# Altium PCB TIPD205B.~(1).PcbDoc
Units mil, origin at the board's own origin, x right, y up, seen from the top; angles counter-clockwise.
Board outline 684.25 x 4724.41 mil, 4 copper layers (Top Layer, Signal Layer 1, Signal Layer 2, Bottom Layer), stack 61.6 mil thick; 36 components, 24 nets, 156 pads, 59 vias.
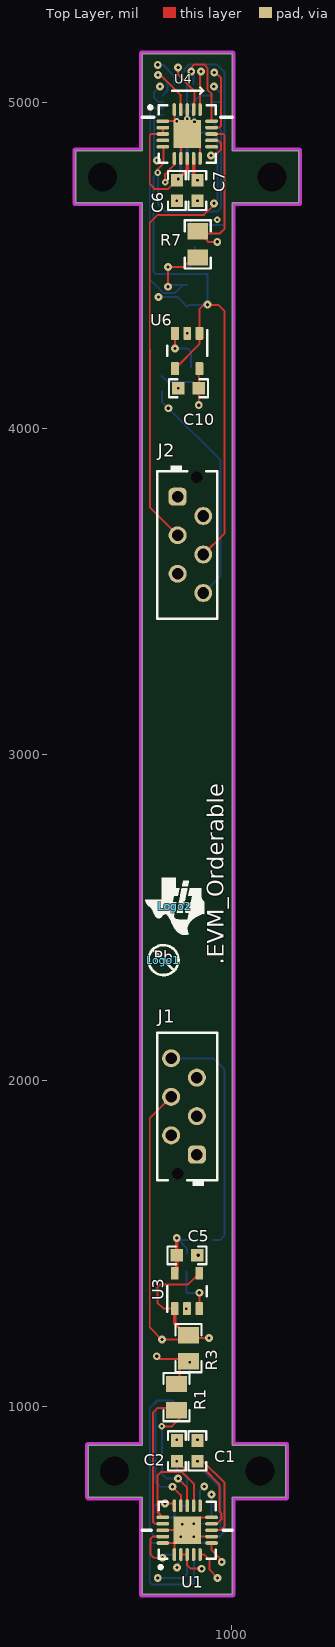
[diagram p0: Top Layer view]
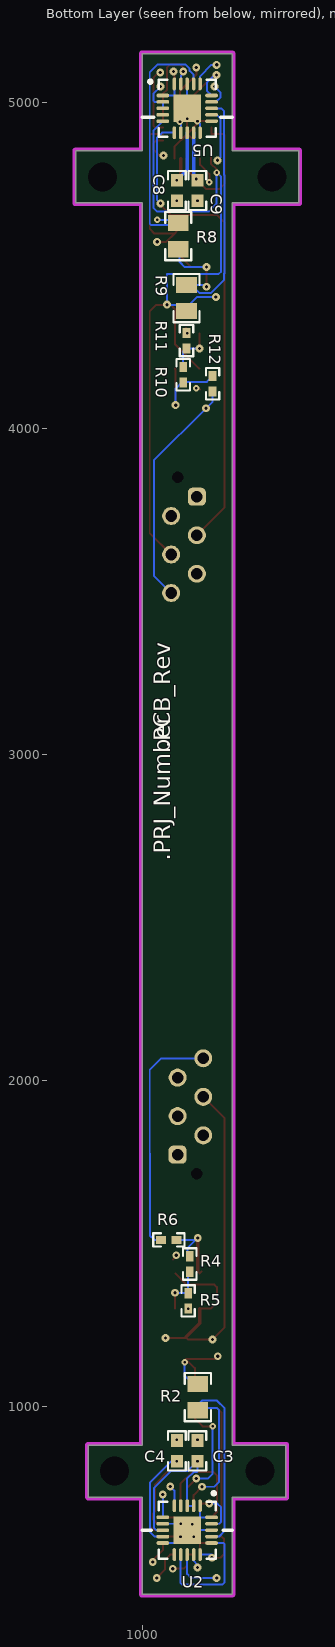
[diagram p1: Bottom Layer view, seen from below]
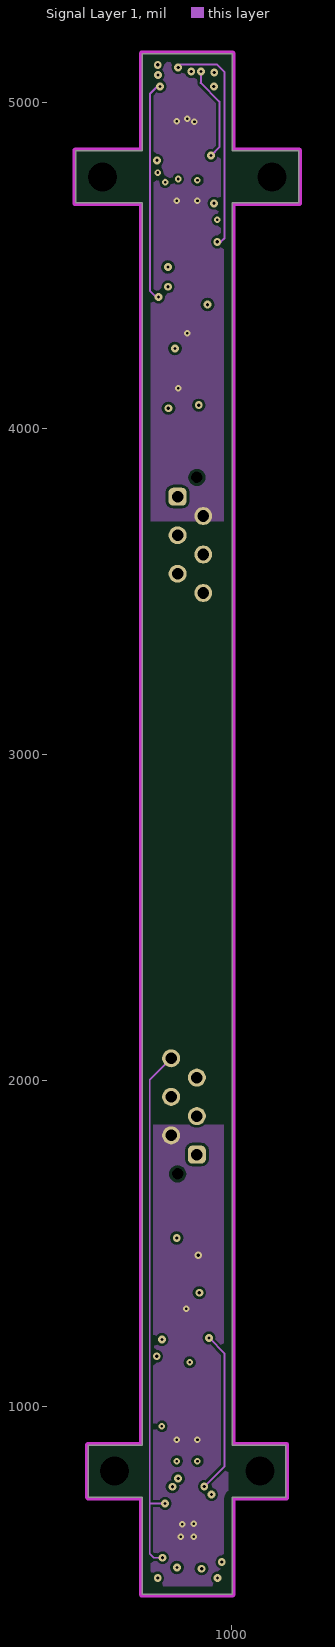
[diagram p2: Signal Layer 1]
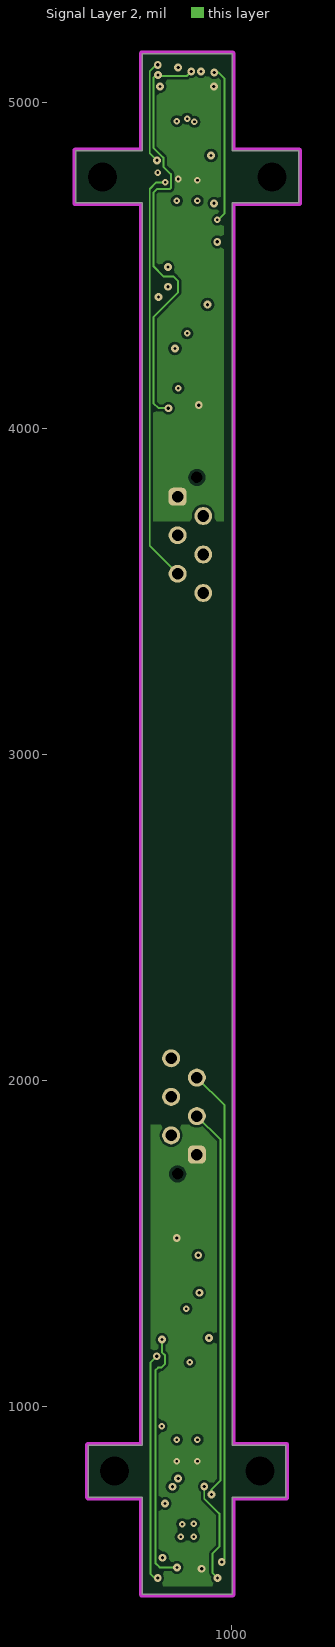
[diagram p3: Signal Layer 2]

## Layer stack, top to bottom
Top Solder: solder mask 0.4, Solder Resist, Dk 3.5
Top Layer: signal copper 1.4
Dielectric 1: prepreg 8, FR-4, Dk 4.2
Signal Layer 1: signal copper 1.4
Dielectric 2: core 40, FR-4, Dk 4.2
Signal Layer 2: signal copper 1.4
Dielectric 3: prepreg 8, FR-4, Dk 4.2
Bottom Layer: signal copper 1.4
Bottom Solder: solder mask 0.4, Solder Resist, Dk 3.5

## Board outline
725,425 725,723.03 560.04,723.03 560.04,882.87 725,882.87 725,4691.54 520.67,4691.54 520.67,4851.38 725,4851.38 725,5149.41 1000.59,5149.41 1000.59,4851.38 1204.92,4851.38 1204.92,4691.54 1000.59,4691.54 1000.59,882.87 1165.55,882.87 1165.55,723.03 1000.59,723.03 1000.59,425

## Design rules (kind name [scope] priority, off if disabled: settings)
AcuteAngle [All] p1: minimum=4.50000000000000E+0001 checktracksonly=FALSE
AssemblyTestPointUsage [All] p1: valid=2
Clearance Clearance_Keepouts [((IsTrack Or IsArc) And Not InPoly) And IsFree and IsKeepOut vs ((IsTrack Or IsArc) And Not InPoly) And IsFree and IsKeepOut] p1: gap=0
Clearance Clearance_BoardEdge_MountingHoles [OnCopper and InComponentClass('Mounting Holes') vs IsKeepOut] p2: gap=40
Clearance Clearance_BoardEdge_Poly [OnCopper and InPoly vs IsKeepOut] p3: gap=25
Clearance Clearance_BoardEdge [OnCopper and Not InComponentClass('Logo') and not InComponentClass('FiducialMark') and not InRegion(1000,500,4000,800) and Not IsKeepout vs IsKeepOut] p4: gap=20
Clearance Clearance_Poly [InPolygon] p5: gap=8
Clearance [All] p6: gap=4.9
ComponentClearance ComponentClearance_MountingHoles_FiducialMarks [InComponentClass('Mounting Holes') vs InComponentClass('FiducialMark')] p1: gap=7 collisioncheckmode=3 verticalgap=10 showdistances=FALSE
ComponentClearance ComponentClearance_Shunt [InComponentClass('Header') vs InComponentClass('Shunt')] p2: gap=0 collisioncheckmode=3 verticalgap=0 showdistances=FALSE
ComponentClearance ComponentClearance_Logo [InComponentClass('Logo')] p3: gap=0 collisioncheckmode=3 verticalgap=0 showdistances=FALSE
ComponentClearance ComponentClearance_ScrewToNut [(HasFootprint('NY PMS 440 0025 PH')) vs (HasFootprint('Keystone_1902C'))] p4: gap=5 collisioncheckmode=3 verticalgap=10 showdistances=FALSE
ComponentClearance ComponentClearance_MountingHoles [InComponentClass('Mounting Holes') vs InAnyComponent And Not InComponentClass('Hardware')] p5: gap=10 collisioncheckmode=3 verticalgap=10 showdistances=TRUE
ComponentClearance ComponentClearance_SmallPassives [HasFootprint('0201*') or HasFootprint('0402*') or HasFootprint('0508') or HasFootprint('0603*') or HasFootprint('0612') or HasFootprint('0805*') or HasFootprint('0815*') or HasFootprint('0830*') or HasFootprint('1206*') or HasFootprint('1210*') or HasFootprint('1808*') or HasFootprint('1812*') or HasFootprint('1825*') or HasFootprint('2010*') or HasFootprint('2220*') or HasFootprint('2225*') or HasFootprint('2512*') or HasFootprint('2728*') or HasFootprint('3518*') vs HasFootprint('0201*') or HasFootprint('0402*') or HasFootprint('0508') or HasFootprint('0603*') or HasFootprint('0612') or HasFootprint('0805*') or HasFootprint('0815*') or HasFootprint('0830*') or HasFootprint('1206*') or HasFootprint('1210*') or HasFootprint('1808*') or HasFootprint('1812*') or HasFootprint('1825*') or HasFootprint('2010*') or HasFootprint('2220*') or HasFootprint('2225*') or HasFootprint('2512*') or HasFootprint('2728*') or HasFootprint('3518*')] p6: gap=20 collisioncheckmode=3 verticalgap=10 showdistances=FALSE
ComponentClearance ComponentClearance_THtoSMT [IsThruComponent And  Not InComponentClass('Hardware') vs IsSMTComponent And  Not InComponentClass('Hardware')] p7: gap=10 collisioncheckmode=3 verticalgap=10 showdistances=FALSE
ComponentClearance ComponentClearance_THtoTH [IsThruComponent vs IsThruComponent] p8: gap=10 collisioncheckmode=3 verticalgap=10 showdistances=FALSE
ComponentClearance [Not InComponentClass('Hardware') And  Not InComponentClass('Logo') vs Not InComponentClass('Hardware') And  Not InComponentClass('Logo')] p9: gap=7 collisioncheckmode=3 verticalgap=7 showdistances=TRUE
DiffPairsRouting [All] p1: maxlimit=100 minlimit=10 mostfreqgap=10 toplayer_minwidth=15 toplayer_maxwidth=15 toplayer_prefwidth=15 midlayer1_minwidth=15 midlayer1_maxwidth=15 midlayer1_prefwidth=15 midlayer2_minwidth=15 midlayer2_maxwidth=15 midlayer2_prefwidth=15 bottomlayer_minwidth=15 bottomlayer_maxwidth=15 bottomlayer_prefwidth=15 maxuncoupledlength=1000
FabricationTestPointUsage TestPointUsage [All] p1: valid=2 allowmultiple=FALSE
FabricationTestpoint Testpoint [All] p1: side=3 testpointundercomponent=TRUE minsize=40 maxsize=100 preferedsize=60 minholesize=0 maxholesize=40 preferedholesize=32 testpointgrid=1 allowsidetop=TRUE allowsidebottom=TRUE usegrid=TRUE gridtolerance=0.01
FanoutControl Fanout_LCC [IsLCC] p1: bgadir=Out bgaviamode=Centered fanoutstyle=Auto fanoutdirection=Alternating viagrid=1 // Fanout_LCC (Default Rule)
FanoutControl Fanout_BGA [IsBGA] p2: bgadir=Out bgaviamode=Centered fanoutstyle=Auto fanoutdirection=Alternating viagrid=1 // Fanout_BGA (Default Rule)
FanoutControl Fanout_Default [All] p4: bgadir=Out bgaviamode=Centered fanoutstyle=Auto fanoutdirection=Alternating viagrid=1 // Fanout_Default (Default Rule)
FanoutControl Fanout_Small [(CompPinCount < 5)] p5: bgadir=Out bgaviamode=Centered fanoutstyle=Auto fanoutdirection=OutThenIn viagrid=1 // Fanout_Small (Default Rule)
Height [All] p1 off: minheight=0 maxheight=1000 prefheight=500
HoleSize [All] p1: absolutevalues=TRUE maxlimit=251 minlimit=8 maxpercent=80.000 minpercent=20.000
MinimumAnnularRing MinimumAnnularRing_ThermalPadVias [IsVia and InAnyComponent] p1: minimumring=5.91
MinimumAnnularRing [All] p2: minimumring=6
MinimumSolderMaskSliver MinimumSolderMaskSliver_Logo [InComponentClass('Logo') vs InComponentClass('Logo')] p1: minsoldermaskwidth=0.7
MinimumSolderMaskSliver [All] p2: minsoldermaskwidth=3.1
PlaneConnect [All] p1: planeconnectstyle=Relief reliefexpansion=10 reliefentries=4 reliefconductorwidth=10 reliefairgap=10
PolygonConnect [All] p1: connectstyle=Direct reliefconductorwidth=10 reliefentries=4 polygonreliefangle="90 Angle" airgapwidth=10
RoutingVias ThermalPadVias [IsVia and InAnyComponent] p1: holewidth=8 width=19.68 viastyle="Through Hole" minholewidth=7.87 minwidth=19.68 maxholewidth=999 maxwidth=999
RoutingVias [All] p2: holewidth=10 width=24 viastyle="Through Hole" minholewidth=8 minwidth=20 maxholewidth=999 maxwidth=999
SilkToSilkClearance SilkToSilkClearance_Pb-FreeLogo [(HasFootprint('Pb-Free_Overlay_Medium') OR HasFootprint('Pb-Free_Overlay_Small')) vs (HasFootprint('Pb-Free_Overlay_Medium') OR HasFootprint('Pb-Free_Overlay_Small'))] p1 off: silktosilkclearance=0
SilkToSilkClearance [All] p2 off: silktosilkclearance=3
SilkToSolderMaskClearance SilkToComonentPadClearance [IsPad and InAnycomponent vs Not InComponentClass('Hardware')] p1: minsilkscreentomaskgap=3 clearancetoexposedcopper=TRUE
SilkToSolderMaskClearance "Silk to Solder Mask Opening" [Not InComponentClass('Hardware') vs Not InComponentClass('Hardware')] p2: minsilkscreentomaskgap=3 clearancetoexposedcopper=FALSE
SolderMaskExpansion [All] p1: expansion=0
Width [All] p1: maxlimit=100 minlimit=6 preferedwidth=6 minimp=50.000000 maximp=50.000000 favimp=50.000000 checkconnectedcopper=TRUE
15 further rules are at their usual default settings.

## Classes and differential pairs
component class Logo: Logo2
component class TIPD205BHW: Logo1 Logo2 Logo3 Logo? ZZ2 ZZ3 ZZ4
component class AssemblyNote: ZZ2 ZZ3 ZZ4

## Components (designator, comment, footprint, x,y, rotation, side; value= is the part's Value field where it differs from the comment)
C1 "C0603C105K3RACTU" 0603 894.29,864.92 r90 top
C2 "C0603C105K3RACTU" 0603 831.3,864.92 r270 top
C3 "C0603C105K3RACTU" 0603 831.3,864.92 r90 bottom
C4 "C0603C105K3RACTU" 0603 894.29,864.92 r270 bottom
C5 "C0603C105K3RACTU" 0603 862.05,1464.61 r0 top
C6 "C0603C105K3RACTU" 0603 831.3,4729.72 r270 top
C7 "C0603C105K3RACTU" 0603 894.29,4729.7 r90 top
C8 "C0603C105K3RACTU" 0603 894.29,4729.7 r270 bottom
C9 "C0603C105K3RACTU" 0603 831.3,4729.72 r90 bottom
C10 "C0603C105K3RACTU" 0603 866.73,4123.43 r180 top
J1 "292207-6" TE_292207-6 862.8,1921.06 r90 top
J2 "292207-6" TE_292207-6 862.8,3643.11 r270 top
Logo1 "Pb-Free Symbol" Pb-Free_Overlay_Small 790,2370 r0 top
Logo2 "Texas Instruments" TI_Symbol_Overlay_Small 825,2535 r0 top
Logo3 "FCC disclaimer" FCC_disclaimer -2112.55,3535 r180 bottom
R1 "RC0805FR-075R11L" 0805_HV 830,1030 r270 top
R2 "RC0805FR-075R11L" 0805_HV 830,1030 r90 bottom
R3 "RT0805BRD0749R9L" 0805_HV 866.73,1179.88 r270 top
R4 "CRCW040210K0FKED" 0402 855,1437.99 r90 bottom
R5 "CRCW040210K0FKED" 0402 860,1325 r90 bottom
R6 "CRCW040210K0FKED" 0402 919.25,1511.89 r180 bottom
R7 "RC0805FR-075R11L" 0805_HV 895,4564.39 r90 top
R8 "RC0805FR-075R11L" 0805_HV 890,4589.98 r270 bottom
R9 "RT0805BRD0749R9L" 0805_HV 865,4400 r90 bottom
R10 "CRCW040210K0FKED" 0402 875,4164.76 r270 bottom
R11 "CRCW040210K0FKED" 0402 865,4269.12 r270 bottom
R12 "CRCW040210K0FKED" 0402 785,4137.17 r90 bottom
U1 "DRV425RTJR" RTJ20_no_vias 862.8,621.85 r90 top
U2 "DRV425RTJR" RTJ20_no_vias 862.8,621.85 r270 bottom
U3 "OPA320AIDBVT" DBV0005A_N 862.05,1355.32 r90 top
U4 "DRV425RTJR" RTJ20_no_vias 862.8,4902.95 r0 top
U5 "DRV425RTJR" RTJ20_no_vias 862.8,4981.69 r180 bottom
U6 "OPA320AIDBVT" DBV0005A_N 862.8,4237.6 r270 top
ZZ2 "This Assembly Note will show in the PcbDoc and associated outputs" AssemblyNote 2730,4704.11 r0 top
ZZ3 "This Assembly Note will show in the PcbDoc and associated outputs" AssemblyNote 2730,4615.56 r0 top
ZZ4 "This Assembly Note will show in the PcbDoc and associated outputs" AssemblyNote 2730,4527 r0 top

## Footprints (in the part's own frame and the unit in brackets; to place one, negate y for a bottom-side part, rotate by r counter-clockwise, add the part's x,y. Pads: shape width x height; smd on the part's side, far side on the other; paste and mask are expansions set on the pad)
0402 [mm] "0402 from SM-752 data"
  rect 0.8x0.6 smd: 1(-0.6,0) 2(0.6,0)
  silkscreen extent -1.22,-0.52 1.22,0.52, body extent -0.55,-0.3 0.55,0.3, height 0.6
0603 [mm] "0603 from SM-752 data"
  rect 1x0.95 smd: 1(-0.8,0) 2(0.8,0)
  silkscreen extent -1.52,-0.69 1.52,0.69, body extent -0.87,-0.47 0.87,0.47, height 1
0805_HV [mil] "0805 with 30mil clearance between pads"
  rect 50x63 smd: 1(-40,0) 2(40,0)
  silkscreen extent -74,-40 74,40, body extent -43,-29 43,29, height 57
AssemblyNote [mil] "Assembly Note"
DBV0005A_N [mm] "SOT23, 5-Leads, Body 2.9x1.6mm, Pitch 0.95mm, Lead Span 2.8mm, IPC Medium Density"
  rrect17% 1x0.6 smd: 1(-1.375,0.95) 2(-1.375,0) 3(-1.375,-0.95) 4(1.375,-0.95) 5(1.375,0.95)
  silkscreen extent -1.63,-1.55 0.38,1.55, body extent -1.42,-1.46 1.42,1.46, height 1.09
FCC_disclaimer [mil]
Pb-Free_Overlay_Small [mil]
  silkscreen extent -46,-46 46,46
RTJ20_no_vias [mm]
  oval 1x0.28 smd paste-0.025 mask+0.07: 1(-1.9,1) 2(-1.9,0.5) 3(-1.9,0) 4(-1.9,-0.5) 5(-1.9,-1) 11(1.9,-1) 12(1.9,-0.5) 13(1.9,0) 14(1.9,0.5) 15(1.9,1)
  oval 0.28x1 smd paste-0.025 mask+0.07: 6(-1,-1.9) 7(-0.5,-1.9) 8(0,-1.9) 9(0.5,-1.9) 10(1,-1.9) 16(1,1.9) 17(0.5,1.9) 18(0,1.9) 19(-0.5,1.9) 20(-1,1.9)
  rect 2.15x2.15 smd paste-1.075 mask+0.07: 21(0,0)
  silkscreen extent -3,-2.23 2.23,2.22, body extent -2.07,-2.08 2.08,2.07, height 0.8
TE_292207-6 [mm] "Header(shrouded), 1.5mm, 6x1, TH"
  rrect50% 1.4x1.4 hole 0.9: 1(-3.75,-0.75)
  round 1.4 hole 0.9: 2(-2.25,1.25) 3(-0.75,-0.75) 4(0.75,1.25) 5(2.25,-0.75) 6(3.75,1.25)
  round 0 hole 0.9 unplated: MH(-5.25,0.75)
  silkscreen extent -6.2,-2.35 5.75,2.35, body extent -5.75,-2.35 5.75,2.35, height 6.9
TI_Symbol_Overlay_Small [mil]
  silkscreen extent -90,-88 91,88

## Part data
C1 C2 C3 C4 C5 C6 C7 C8 C9 C10: "CAP, CERM, 1 µF, 25 V, +/- 10%, X7R, 0603"
J1 J2: "Header(shrouded), 1.5mm, 6x1, Tin, TH"
Logo1: library part Pb-Free
Logo2: library part TI_Logo, "Texas Instrument Corporate Signature"
Logo3: library part FCC_disclaimer, "FCC_disclaimer"
R1 R2 R7 R8: "RES, 5.11, 1%, 0.125 W, 0805"
R3 R9: "RES, 49.9, 0.1%, 0.125 W, 0805"
R4 R5 R6 R10 R11 R12: "RES, 10.0 k, 1%, 0.063 W, 0402"
U1 U2 U4 U5: "Fully Integrated Precision Fluxgate Magnetic Field Sensor and readout, RTJ0020G (WQFN-20)"
U3 U6: "Precision, 20 MHz, 0.9 pA Ib, RRIO, CMOS Operational Amplifier, 1.8 to 5.5 V, -40 to 125 degC, 5-pin SOT23 (DBV0005A), Green (RoHS & no Sb/Br)"
ZZ2 ZZ3 ZZ4: library part AssemblyNote

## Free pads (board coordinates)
  round 0 hole 88.98 unplated: 5(602.56,4771.46) 5(639.17,802.95) 5(1086.42,802.95) 5(1123.03,4771.46)

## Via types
v1: diameter 24, hole 10, Top Layer to Bottom Layer, 24 vias
v2: diameter 20, hole 8, Top Layer to Bottom Layer, 19 vias
v3: diameter 24, hole 10, Top Layer to Bottom Layer, tented both sides, 12 vias
v4: diameter 20, hole 8, Top Layer to Bottom Layer, tented both sides, 4 vias

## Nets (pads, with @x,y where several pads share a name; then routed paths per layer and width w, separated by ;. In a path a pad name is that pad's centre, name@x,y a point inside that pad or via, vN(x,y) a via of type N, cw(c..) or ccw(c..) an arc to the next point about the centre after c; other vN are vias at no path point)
GND_H: C6.2 C7.1 C8.2 C9.1 C10.2 J2.2 R11.1 U4.1 U4.7 U4.10 U4.18 U4.20 U4.21 U5.1 U5.7 U5.10 U5.18 U5.20 U5.21 U6.2 | length 784.7
  Top Layer w6: U4.1 823.43,4942.32 U4.20 ; C10.2@823.7,4119.76 C10.2@835.24,4131.3 ; U4.21@827.36,4938.39 U4.21 ; U4.7 843.11,4883.27 U4.21 ; U4.21@862.8,4915 U4.18@862.8,4989.8 ; U6.2@865,4286.84 866.73,4288.57 U6.2@866.73,4308.46 ; U4.10 902.17,4863.58 U4.21
  Bottom Layer w6: U5.10 823.43,4934.45 v4(831.3,4942.32) 831.3,4950.2 U5.21 ; R11.1@862.22,4292.75 R11.1@862.8,4293.32 ; U5.18 U5.21 ; U5.7 882.48,4962.01 U5.21 ; U5.20 U5.21@902.17,5021.06 ; U5.1 U5.21@902.17,5021.06 ; U5.21 U5.21@902.17,5021.06
  other v2: 835.24,4123.43 862.8,4291.73 831.3,4698.23 894.29,4698.21
  other v4: 885,4940 862.8,4950
GND_V: C1.2 C2.1 C3.2 C4.1 C5.2 J1.2 R5.1 U1.1 U1.7 U1.10 U1.18 U1.20 U1.21 U2.1 U2.7 U2.10 U2.18 U2.20 U2.21 U3.2 | length 518.7
  Top Layer w6: U1.18 U1.21@860.59,621.85 ; U1.20@788.94,582.48 824.37,582.48 U1.1@824.37,547.05 ; v2(860,1301.38) U3.2@860,1307.32 ; U3.2 U3.2@862.05,1305.27 ; v2(883.42,602.17) U1.7 U1.7@938.54,602.17 ; C5.2 C5.2@906.26,1451.89 ; U1.21@899.96,661.22 U1.10
  Bottom Layer w6: U2.18 U2.21 ; U2.20 823.43,661.22 U2.1 ; U2.21@854.08,613.13 U2.21@858.36,608.85 ; v2(860,1301.38) R5.1@860,1307.52 ; U2.21@872.46,631.51 U2.21@876.74,627.24 ; v2(882.48,641.54) U2.7 ; U2.21@902.17,582.48 U2.10
  other v1: 896.48,1464.61
  other v2: 843.11,601.14 847.05,640.51 831.3,899.35 894.29,899.37
NetJ1_6: J1.6 R6.1 U1.15 U1.19 U2.15 U2.19 | length 2688.7
  Top Layer w6: v3(787.24,537.24) 760.76,537.24 750,548 750,595 757.17,602.17 U1.19 ; v3(795,703.54) 816.54,703.54 U1.15
  Signal Layer 1 w6: v3(787.24,537.24) 760.76,537.24 748,550 748,705 ; v3(795,703.54) 749.46,703.54 748,705 ; J1.6 748,2003.12 748,705
  Bottom Layer w6: v3(787.24,537.24) 787.24,547.05 U2.15 ; U2.19 764.96,641.54 758.85,647.64 758.85,692.39 770,703.54 v3(795,703.54) ; J1.6 942.83,2068.7 977.59,2033.94 976.84,1525.27 963.46,1511.89 R6.1
NetJ2_6: J2.6 R12.1 U4.15 U4.19 U5.15 U5.19 | length 2571.9
  Top Layer w6: v3@769.72,5087.27 769.72,5089.29 772.59,5092.17 843.11,5021.65 842.9,5021.43 842.9,4977.97 U4.19 ; v3(875,5094.76) 875,5106.17 885,5116.17 914.38,5116.17 924.9,5105.65 924.9,5066.52 924.59,5066.21 924.59,5038.94 937.6,5025.92 U4.15
  Signal Layer 2 w6: v3@770.28,5087.27 770,5087.56 769.72,5087.27 769.72,5086.71 758.9,5075.89 758.9,4861.41 789.9,4830.41 789.9,4803.15 812.9,4780.15 812.9,4737.47 809.19,4733.76 769.35,4733.76 758.9,4723.31 758.9,4498.27 791.22,4465.94 821.22,4465.94 834.25,4452.91 834.25,4416.42 759.21,4341.38 759.21,4077.95 775,4062.17 v1(805,4062.17) ; v3@772.59,5089.58 770,5086.99 776.65,5080.34 860.58,5080.34 v3(875,5094.76)
  Bottom Layer w6: v3@769.72,5091.88 769.72,5087.27 774.89,5087.27 802.17,5060 802.17,5035.28 U5.15 ; R12.1 785,4082.17 v1(805,4062.17) 965,3902.17 965,3548.46 J2.6 ; v3@870,5094.76 882.48,5082.28 U5.19
  other v3: 773.32,5083.67
NetR1_1: R1.1 R2.2 R3.2 U2.13 | length 1131.4
  Top Layer w6: v1(769.21,1155) 777.8,1146.42 866.73,1146.42 839.17,1118.86 R1.1@839.17,1063.74
  Signal Layer 2 w6: v1(769.21,1155) 750,1135.79 750,488.9 763.9,475 v1@770,475
  Bottom Layer w6: v1@770,475 850,475 862.8,487.8 U2.13 ; R2.2@839.17,1063.74 870.67,1095.24 v2@870.67,1129.72
  other v1: 772.5,475
  other v2: 870,1136.57
NetR1_2: R1.2 U1.13 U1.17 | length 850
  Top Layer w6: v2(785,940) 815.83,940 839.17,963.35 839.17,996.81 771.81,996.81 757.44,982.44 757.44,647.44 763.35,641.54 U1.17 U1.17@788.94,641.54 ; v1(835,780) 862.8,752.2 U1.13
  Bottom Layer w6: v2(785,940) 785,795 800,780 v1(835,780)
NetR2_1: R2.1 U1.14 U2.17 | length 959.2
  Top Layer w6: v1(817.55,755) 843.11,729.44 U1.14
  Bottom Layer w5.91: 748,714.77 748,619.48 765.31,602.17 U2.17@788.94,602.17
  Bottom Layer w6: 748,714.77 748,995.81 771.68,1019.49 816.5,1019.49 839.17,996.81 771.81,996.81 765,990 765,770.55 780.55,755 v1(817.55,755)
NetR4_1: R4.1 R5.2 U3.3 | length 155.4
  Top Layer w6: U3.3 900,1301.73 v1(900,1350)
  Bottom Layer w6: R4.1@860,1414.37 R5.2 898.62,1348.62 v1(900,1350)
NetR7_1: R7.1 R8.2 R9.2 U5.13 | length 1042.6
  Top Layer w6: v1(803.74,4434.45) v1(803.74,4495) 850.51,4495 R7.1@886.42,4530.91
  Bottom Layer w6: 749.51,4932.17 749.51,4777.53 748,4776.01 748,4476.59 749.51,4475.07 749.51,4456.58 791.1,4415 825,4415 R9.2@850.35,4440.35 ; 749.49,4932.2 749.49,4952.4 ; 749.51,4952.43 749.51,4973.21 758,4981.69 U5.13 ; v1(803.74,4434.45) 809.65,4440.35 R9.2@850.35,4440.35 ; v1(803.74,4495) 870,4495 886.42,4511.42 R8.2@886.42,4556.52 ; R9.2@862.8,4440.35 R9.2@850.35,4440.35
NetR7_2: R7.2 U4.13 U4.17 | length 1323.3
  Top Layer w6: v1@835,5104.76 835,5084.76 884.9,5034.86 884.9,4980.18 U4.17 ; R7.2 R7.2@901.56,4597.83 ; U4.13 973.65,4902.95 977.59,4899.02 977.59,4612.24 963.19,4597.83 R7.2@901.56,4597.83 ; v3(955,4572.24) 927.15,4572.24 R7.2@901.56,4597.83
  Signal Layer 1 w6: v1@835,5109.76 841.41,5116.17 953.83,5116.17 977.59,5092.41 977.59,4584.06 965.78,4572.24 v3(955,4572.24)
  other v1: 835,5107.17
NetR8_1: R8.1 U4.14 U5.17 | length 1565
  Top Layer w6: U4.14 961.11,4922.64 966.38,4927.9 966.38,5074.96 945.47,5095.87 v1(945.47,5091.92)
  Signal Layer 2 w6: v1(945.47,5091.92) 957.91,5091.92 977.59,5072.24 977.59,4658.86 976.97,4658.86 v2@957.93,4639.82
  Bottom Layer w6: U5.17 843.11,5084.73 855.1,5096.72 855.1,5103.01 868.27,5116.17 953.83,5116.17 977.59,5092.41 977.59,4627.99 973.05,4623.45 862.8,4623.45 879.17,4639.82 v2@957.93,4639.82
  other v2: 955,4639.82
NetR10_1: R10.1 R11.2 U6.3 | length 144.7
  Top Layer w6: v1(825,4245.5) U6.3
  Bottom Layer w6: v1(825,4245.5) R11.2@862.22,4245.5 ; R11.2 875,4235.5 R10.1
NetU1_12: U1.12 U1.16 | length 333.4
  Top Layer w6: U1.16 771.68,677.54 771.68,790 781.68,800 847.01,800 883.43,763.58 U1.12@883.43,696.65
NetU2_12: U2.12 U2.16 | length 386.2
  Bottom Layer w6: U2.16 752.48,582.48 748,578 748,462 755.15,454.85 878.54,454.85 883.72,460.02 883.72,545.81 U2.12
NetU4_12: U4.12 U4.16 | length 515.5
  Top Layer w6: U4.16 902.17,5091.93 v3(905,5094.76) 906.35,5094.76 911.35,5089.76 v3@910.68,5089.09 ; v3(935.79,4836.95) 935.79,4838.18 942.2,4831.77 966.67,4856.24 966.67,4873.88 957.28,4883.27 U4.12
  Signal Layer 1 w6: v3(905,5094.76) 905,5060.32 904.1,5059.42 961.22,5002.3 961.22,4862.38 v3(935.79,4836.95)
NetU5_12: U5.12 U5.16 | length 568.4
  Signal Layer 2 w6: v3(770,4822.17) 748,4844.17 748,5095.24 767.76,5115 v1@770,5115
  Bottom Layer w6: v3(770,4822.17) 760.43,4831.73 760.43,4936.66 760.39,4936.71 760.39,4947.89 760.43,4947.93 760.43,4950.2 772.24,4962.01 U5.12 ; v1@770,5115 788.54,5115 823.43,5080.12 U5.16
  other v1: 772.5,5115
VCM_H: J2.5 U4.6 | length 1364.8
  Top Layer w6: v4(795,4754.76) 795,4779.76 823.43,4808.19 U4.6
  Signal Layer 1 w6: v4@794.26,4763.55 795,4762.8 v4(795,4754.76)
  Signal Layer 2 w6: v4(795,4754.76) 768.48,4754.76 748,4734.28 748,3639.8 J2.5
VCM_V: J1.5 U1.6 | length 1596.2
  Top Layer w6: U1.6 937.6,560.79 968.59,529.79 v3(968.59,523.9)
  Signal Layer 2 w6: J1.5 977.59,1924.38 977.59,532.9 v3(968.59,523.9)
VDD_H: C6.1 C7.2 C8.1 C9.2 C10.1 J2.1 R10.2 R12.2 U4.2 U4.3 U4.8 U4.9 U5.2 U5.3 U5.8 U5.9 U6.5 | length 1163.7
  Top Layer w6: U4.2 U4.3 751.94,4902.95 748,4899.02 748,4749.76 764,4733.76 803.84,4733.76 C6.1 ; C7.2@882.48,4773.01 v2(894.29,4761.2) ; v1(898.23,4071.54) C10.1 898.23,4181.5 U6.5
  Top Layer w10: v2(835.04,4764.96) 862.8,4792.72 U4.8 ; C7.2@882.48,4773.01 U4.9
  Bottom Layer w6: R12.2 802.68,4143.11 877.65,4143.11 898.23,4122.54 v1(898.23,4071.54) ; C9.2 C9.2@843.11,4773.03 ; U5.8@862.58,4906.67 U5.8 ; U5.3 U5.2 962.88,5001.42 966.38,5004.92 966.38,5010.47 966.67,5010.76 966.67,5026.1 944.49,5048.28 v3(944.49,5048.62)
  Bottom Layer w10: C9.2@843.11,4773.03 U5.9 ; U5.8 862.8,4792.7 v2(894.29,4761.2)
VDD_V: C1.1 C2.2 C3.1 C4.2 C5.1 J1.1 R4.2 R6.2 U1.2 U1.3 U1.8 U1.9 U2.2 U2.3 U2.8 U2.9 U3.5 | length 1734.8
  Top Layer w6: U3.5@818.74,1415.35 U3.5 U3.5@830.55,1415.35 ; v2(831.3,833.43) 859.79,804.94 918.84,804.94 961.22,762.56 961.22,679.77 967.28,673.71 967.28,654.8 961.22,648.73 961.22,648.07 954.69,641.54 U1.9 ; U1.2 U1.3 862.8,514.53 873.58,503.74 v1(907.05,503.74) ; v2(894.29,833.43) 911.02,833.43 977.59,766.86 977.59,633.34 966.1,621.85 U1.8@938.54,621.85
  Top Layer w10: U3.5@830.55,1415.35 v1(830.55,1517.76)
  Bottom Layer w6: v1(830.55,1517.76) v1@836.42,1511.89 ; U2.2 U2.3 862.8,780.35 843.24,799.9 833.33,799.9 831.3,801.93 v2(831.3,833.43) 860.83,803.9 912.01,803.9 965.16,750.75 965.16,666.88 965.2,666.83 965.2,635.97 965.16,635.92 965.16,628.7 958.31,621.85 U2.8 ; R4.2@862.05,1470.51 862.05,1486.26 v1@836.42,1511.89 ; v2(894.29,833.43) 911.02,833.43 976.97,767.48 976.97,616.89 962.24,602.17 U2.9 ; R6.2 v1@836.42,1511.89
VOUT_H: J2.3 U5.6 | length 1482.9
  Top Layer w6: J2.3 748,3757.9 748,3857.51 748,4630.68 772.28,4654.96 914.01,4654.96 945,4685.94 v1(945,4690.35)
  Bottom Layer w6: U5.6 939.88,4906.93 955.69,4891.12 955.69,4701.05 v1(945,4690.35)
VOUT_V: J1.3 U2.6 | length 1271.8
  Signal Layer 2 w6: J1.3 965,1818.86 965,774.21 937.6,746.81 v1(937.6,731.06)
  Bottom Layer w6: U2.6 v1(937.6,731.06)
VREF_H: J2.4 R9.1 U4.5 U5.5 U5.14 U6.1 U6.4 | length 3231.5
  Top Layer w6: v2(772.24,4784.84) 772.24,4794.36 789.9,4812.01 789.9,4861.67 U4.5 ; U6.4 900.2,4258.27 U6.1 900.2,4365.55 913.98,4379.33 957.28,4379.33 977.59,4359.02 977.59,3679.17 J2.4
  Signal Layer 1 w6: v1@768.31,4402.95 748.62,4422.64 748.62,5025.62 771.62,5048.62 v3(779.13,5048.62)
  Bottom Layer w6: v1@772.24,4402.95 833.27,4402.95 862.8,4373.43 868.7,4379.33 v3@925,4379.33 ; v3(779.13,5048.62) 760.39,5029.87 760.39,5015.5 774.51,5001.38 U5.14 ; v3(925,4379.76) 925,4473.84 766.16,4473.84 758.9,4481.1 758.9,4771.5 v2(772.24,4784.84) 773.07,4784.02 773.07,4688.94 797.01,4665 955.24,4665 966.59,4676.35 966.59,4913.33 U5.5
  other v1: 775,4402.95
VREF_V: J1.4 R3.1 U1.5 U2.5 U2.14 U3.1 U3.4 | length 3107.9
  Top Layer w6: J1.4 748,1885.01 748,1243.5 v1(785.29,1206.2) 859.59,1206.2 866.73,1213.35 868.7,1211.38 v1(929.72,1211.38) ; 824.65,1255.43 825.39,1254.69 ; U3.1 790.2,1301.18 771.5,1319.88 771.5,1367.13 779.37,1375 865,1375 U3.4 ; v1(831.3,507.68) v1@839.17,507.68 ; U1.5@903.11,547.05 914.92,547.05 930.67,531.3 930.67,501.33 v1@957,475
  Top Layer w9.84: 824.65,1276.57 U3.1
  Top Layer w10: 824.65,1255.43 824.65,1276.57 ; 825.39,1254.69 R3.1@866.73,1213.35
  Signal Layer 1 w6: v1(915,755.71) 977.59,818.3 977.59,1163.51 v1(929.72,1211.38)
  Signal Layer 2 w6: v1(785.29,1206.2) 785.29,1167.07 794.9,1157.46 794.9,1131.76 783.24,1120.1 773.55,1120.1 765,1111.55 765,521.2 778.53,507.68 v1(831.3,507.68) ; v1(915,755.71) 915,718.74 961.22,672.52 961.22,571.22 940,550 940,492 v1@957,475
  Bottom Layer w6: v1(831.3,507.68) 831.3,516.24 843.11,528.05 U2.14 ; U2.5 902.17,742.87 v1(915,755.71)
  other v1: 956,475
pads on no net: J1.MH J2.MH U1.4 U1.11 U2.4 U2.11 U4.4 U4.11 U5.4 U5.11
copper on no net: | length 440
  Top Layer w6: -460,7990 -20,7990

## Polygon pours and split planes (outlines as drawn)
VDD_V on Signal Layer 2 "VDD_V_L03_P010" (solid, remove dead copper, pour order 10): 732.87,1865 988.78,1865 988.78,436.81 732.87,436.81
VDD_H on Signal Layer 2 "VDD_H_L03_P009" (solid, remove dead copper, pour order 9): 732.87,5141.54 992.72,5141.54 992.72,3715 732.87,3715
GND_H on Signal Layer 1 "GND_H_L02_P007" (solid, remove dead copper, pour order 7): 732.87,5141.54 992.72,5141.54 992.72,3715 732.87,3715
GND_V on Signal Layer 1 "GND_V_L02_P008" (solid, remove dead copper, pour order 8): 732.87,1865 988.78,1865 988.78,436.81 732.87,436.81

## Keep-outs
Keep-Out Layer:
  lines w10: 515.67,4691.54 ccw(c520.67,4691.54) 520.67,4686.53 ; 515.67,4691.54 ccw(c520.67,4691.54) 520.67,4686.53 ; 515.67,4691.54 ccw(c520.67,4691.54) 520.67,4686.53 ; 515.67,4691.54 ccw(c520.67,4691.54) 520.67,4686.53 ; 515.67,4691.54 515.67,4851.38 ; 515.67,4691.54 515.67,4851.38 ; 515.67,4851.38 cw(c520.67,4851.38) 520.67,4856.38 ; 515.67,4851.38 cw(c520.67,4851.38) 520.67,4856.38 ; 515.67,4851.38 cw(c520.67,4851.38) 520.67,4856.38 ; 515.67,4851.38 cw(c520.67,4851.38) 520.67,4856.38 ; 520.67,4686.53 720,4686.53 ; 520.67,4686.53 720,4686.53 ; 520.67,4856.38 720,4856.38 ; 520.67,4856.38 720,4856.38 ; 555.04,723.03 ccw(c560.04,723.03) 560.04,718.03 ; 555.04,723.03 ccw(c560.04,723.03) 560.04,718.03 ; 555.04,723.03 ccw(c560.04,723.03) 560.04,718.03 ; 555.04,723.03 ccw(c560.04,723.03) 560.04,718.03 ; 555.04,723.03 ccw(c560.04,723.03) 560.04,718.03 ; 555.04,723.03 ccw(c560.04,723.03) 560.04,718.03 ; 555.04,723.03 555.04,882.87 ; 555.04,723.03 555.04,882.87 ; 555.04,723.03 555.04,882.87 ; 555.04,882.87 cw(c560.04,882.87) 560.04,887.88 ; 555.04,882.87 cw(c560.04,882.87) 560.04,887.88 ; 555.04,882.87 cw(c560.04,882.87) 560.04,887.88 ; 555.04,882.87 cw(c560.04,882.87) 560.04,887.88 ; 555.04,882.87 cw(c560.04,882.87) 560.04,887.88 ; 555.04,882.87 cw(c560.04,882.87) 560.04,887.88 ; 560.04,718.03 720,718.03 ; 560.04,718.03 720,718.03 ; 560.04,718.03 720,718.03 ; 560.04,887.88 720,887.88 ; 560.04,887.88 720,887.88 ; 560.04,887.88 720,887.88 ; 720,425 ccw(c725,425) 725,420 ; 720,425 ccw(c725,425) 725,420 ; 720,425 ccw(c725,425) 725,420 ; 720,425 ccw(c725,425) 725,420 ; 720,425 ccw(c725,425) 725,420 ; 720,425 ccw(c725,425) 725,420 ; 720,425 ccw(c725,425) 725,420 ; 720,425 ccw(c725,425) 725,420 ; 720,425 720,718.03 ; 720,425 720,718.03 ; 720,425 720,718.03 ; 720,887.88 720,4686.53 ; 720,887.88 720,4686.53 ; 720,4856.38 720,5149.41 ; 720,4856.38 720,5149.41 ; 720,5149.41 cw(c725,5149.41) 725,5154.41 ; 720,5149.41 cw(c725,5149.41) 725,5154.41 ; 720,5149.41 cw(c725,5149.41) 725,5154.41 ; 720,5149.41 cw(c725,5149.41) 725,5154.41 ; 720,5149.41 cw(c725,5149.41) 725,5154.41 ; 720,5149.41 cw(c725,5149.41) 725,5154.41 ; 720,5149.41 cw(c725,5149.41) 725,5154.41 ; 720,5149.41 cw(c725,5149.41) 725,5154.41 ; 725,420 1000.59,420 ; 725,420 1000.59,420 ; 725,420 1000.59,420 ; 725,420 1000.59,420 ; 725,5154.41 1000.59,5154.41 ; 725,5154.41 1000.59,5154.41 ; 725,5154.41 1000.59,5154.41 ; 725,5154.41 1000.59,5154.41 ; 1000.59,420 ccw(c1000.59,425) 1005.59,425 ; 1000.59,420 ccw(c1000.59,425) 1005.59,425 ; 1000.59,420 ccw(c1000.59,425) 1005.59,425 ; 1000.59,420 ccw(c1000.59,425) 1005.59,425 ; 1000.59,420 ccw(c1000.59,425) 1005.59,425 ; 1000.59,420 ccw(c1000.59,425) 1005.59,425 ; 1000.59,420 ccw(c1000.59,425) 1005.59,425 ; 1000.59,420 ccw(c1000.59,425) 1005.59,425 ; 1000.59,5154.41 cw(c1000.59,5149.41) 1005.59,5149.41 ; 1000.59,5154.41 cw(c1000.59,5149.41) 1005.59,5149.41 ; 1000.59,5154.41 cw(c1000.59,5149.41) 1005.59,5149.41 ; 1000.59,5154.41 cw(c1000.59,5149.41) 1005.59,5149.41 ; 1000.59,5154.41 cw(c1000.59,5149.41) 1005.59,5149.41 ; 1000.59,5154.41 cw(c1000.59,5149.41) 1005.59,5149.41 ; 1000.59,5154.41 cw(c1000.59,5149.41) 1005.59,5149.41 ; 1000.59,5154.41 cw(c1000.59,5149.41) 1005.59,5149.41 ; 1005.59,425 1005.59,718.03 ; 1005.59,425 1005.59,718.03 ; 1005.59,718.03 1165.55,718.03 ; 1005.59,718.03 1165.55,718.03 ; 1005.59,887.88 1165.55,887.88 ; 1005.59,887.88 1005.59,4686.53 ; 1005.59,887.88 1005.59,4686.53 ; 1005.59,887.88 1165.55,887.88 ; 1005.59,4686.53 1204.92,4686.53 ; 1005.59,4686.53 1204.92,4686.53 ; 1005.59,4856.38 1204.92,4856.38 ; 1005.59,4856.38 1005.59,5149.41 ; 1005.59,4856.38 1005.59,5149.41 ; 1005.59,4856.38 1204.92,4856.38 ; 1165.55,718.03 ccw(c1165.55,723.03) 1170.55,723.03 ; 1165.55,718.03 ccw(c1165.55,723.03) 1170.55,723.03 ; 1165.55,718.03 ccw(c1165.55,723.03) 1170.55,723.03 ; 1165.55,718.03 ccw(c1165.55,723.03) 1170.55,723.03 ; 1165.55,887.88 cw(c1165.55,882.87) 1170.55,882.87 ; 1165.55,887.88 cw(c1165.55,882.87) 1170.55,882.87 ; 1165.55,887.88 cw(c1165.55,882.87) 1170.55,882.87 ; 1165.55,887.88 cw(c1165.55,882.87) 1170.55,882.87 ; 1170.55,723.03 1170.55,882.87 ; 1170.55,723.03 1170.55,882.87 ; 1204.92,4686.53 ccw(c1204.92,4691.54) 1209.92,4691.54 ; 1204.92,4686.53 ccw(c1204.92,4691.54) 1209.92,4691.54 ; 1204.92,4686.53 ccw(c1204.92,4691.54) 1209.92,4691.54 ; 1204.92,4686.53 ccw(c1204.92,4691.54) 1209.92,4691.54 ; 1204.92,4856.38 cw(c1204.92,4851.38) 1209.92,4851.38 ; 1204.92,4856.38 cw(c1204.92,4851.38) 1209.92,4851.38 ; 1204.92,4856.38 cw(c1204.92,4851.38) 1209.92,4851.38 ; 1204.92,4856.38 cw(c1204.92,4851.38) 1209.92,4851.38 ; 1209.92,4691.54 1209.92,4851.38 ; 1209.92,4691.54 1209.92,4851.38
  text ".Layer_Name" at 577,-858.49 h60

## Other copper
Top Layer:
  text ".Layer_Name" at 577,-858.49 h60
Bottom Layer:
  text ".Layer_Name" at 577,-858.49 h60

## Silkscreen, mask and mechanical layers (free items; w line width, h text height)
Top Overlay:
  lines w6: 902.17,5025.93 912.17,5035.93 902.17,5045.93
  lines w7.09: 817.17,5035.93 912.17,5035.93
  lines w10: 725,621.85 752.56,621.85 ; 725,4954.13 760.43,4954.13 ; 965.16,4954.13 1000.59,4954.13 ; 973.03,621.85 1000.59,621.85
  text ".EVM_Orderable" at 975,2355 h50 r90
  text ".Layer_Name" at 577,-858.49 h60
Bottom Overlay:
  lines w10: 725,621.85 752.56,621.85 ; 725,4954.13 760.43,4954.13 ; 965.16,4954.13 1000.59,4954.13 ; 973.03,621.85 1000.59,621.85
  text ".PCB_Rev" at 915,3020 h50 r270
  text ".PRJ_Number" at 915,2675 h50 r270
  text ".Layer_Name" at 577,-858.49 h60
Top Paste:
  text ".Layer_Name" at 577,-858.49 h60
Bottom Paste:
  text ".Layer_Name" at 577,-858.49 h60
Top Solder:
  lines w10: 823.43,4960.43 823.43,4987.99 ; 831.3,4771.46 834.25,4774.41 839.17,4774.41
  text ".Layer_Name" at 577,-858.49 h60
  text ".Layer_Name" at 577,-858.49 h60
Bottom Solder:
  lines w10: 823.43,4944.69 831.3,4952.56 ; 882.48,4917.17 882.48,4917.17
  text ".Layer_Name" at 577,-858.49 h60
Drill Guide:
  text ".Layer_Name" at 577,-858.49 h60
M1 Board Outline:
  lines w10: 725,2295.08 1000.59,2295.08 ; 730,3279.33 1005.59,3279.33 1119.76,3279.33 1170.94,3330.51 ; 1005.59,2295.08 1119.76,2295.08 1170.94,2346.26 ; 520.67,4691.54 520.67,4851.38 725,4851.38 725,5149.41 1000.59,5149.41 1000.59,4851.38 1204.92,4851.38 1204.92,4691.54 1000.59,4691.54 1000.59,882.87 1165.55,882.87 1165.55,723.03 1000.59,723.03 1000.59,425 725,425 725,723.03 560.04,723.03 560.04,882.87 725,882.87 725,4691.54 520.67,4691.54
  text "score line" at 1180,3327.95 h20
  text "score line" at 1175,2360 h20
  text ".Layer_Name" at 577,-858.49 h60
M2 Board Dimensions:
  rectangle: 0,-275 125,-150
  rectangle: 125,-400 500,-275
  lines w7: 0,-275 1000,-275 ; 125,-400 125,-150 ; 250,-400 250,-150 ; 500,-400 500,-150 ; 750,-400 750,-150 ; 0,-400 1000,-400 1000,-150 0,-150 0,-400
  text ".Layer_Name" at 577,-858.49 h60
M3 3D STEP Top:
  text ".Layer_Name" at 577,-858.49 h60
M4 3D STEP Bottom:
  text ".Layer_Name" at 577,-858.49 h60
M5 Assembly Top:
  lines w10: -292,-930.17 6308,-930.17 ; -292,-726.83 6310,-726.83 ; -292,-523.5 -292,-1133.5 3713,-1133.5 6310,-1133.5 6310,-523.5 -291.5,-523.5 -291.5,-1133.5 1284,-1133.5 ; 2173,-1133.5 2173,-523.5 ; 3440,-726.83 3440,-523.5 ; 4280,-726.83 4280,-523.5 ; 4902,-1140 4902,-937.17
  text "COMPONENTS MARKED 'DNP' SHOULD NOT BE POPULATED." at 1153.5,-318.5 h60
  text "ASSEMBLY VARIANT:" at 1153,-434 h60
  text ".VariantName" at 2189,-434 h60
  text "PCB VIEWED FROM TOP SIDE" at -228.5,-655.67 h60
  text "BOARD #:" at 2248,-655.67 h60
  text ".PRJ_Number" at 2793.5,-655.67 h60
  text "REV:" at 3638,-655.67 h60
  text ".PCB_Rev" at 3929.5,-655.67 h60
  text "SVN REV:" at 4476,-655.67 h60
  text ".VersionControl_RevNumber" at 4982,-655.67 h60
  text "TID #:" at 2248,-859 h60
  text ".TID" at 2793.5,-859 h60
  text "PLOT NAME =" at -228.5,-1064.34 h60
  text ".plot_File_Name" at 577,-1064.34 h60
  text "GENERATED    :" at 2250,-1064.34 h60
  text ".Print_Date" at 3119.5,-1064.34 h60
  text ".Print_Time" at 3848.5,-1064.34 h60
  text "TEXAS INSTRUMENTS" at 5113,-1064.34 h60
M6 Assembly Bottom:
  lines w10: -292.5,-727.33 6309.5,-727.33 ; -290.5,-930.67 6309.5,-930.67 ; 1115.5,-1140.5 1115.5,-937.67 ; 1737.5,-727.33 1737.5,-524 ; 2577.5,-727.33 2577.5,-524 ; 3844.5,-1134 3844.5,-524 ; 4733.5,-1134 6309,-1134 6309,-524 -292.5,-524 -292.5,-1134 2304.5,-1134 6309.5,-1134 6309.5,-524
  text "COMPONENTS MARKED 'DNP' SHOULD NOT BE POPULATED." at 6102,-318 h60
  text ".VariantName" at 5058,-434 h60
  text "ASSEMBLY VARIANT:" at 6097,-434 h60
  text ".VersionControl_RevNumber" at 1035.5,-656.17 h60
  text "SVN REV:" at 1541.5,-656.17 h60
  text ".PCB_Rev" at 2088,-656.17 h60
  text "REV:" at 2379.5,-656.17 h60
  text ".PRJ_Number" at 3224,-656.17 h60
  text "BOARD #:" at 3769.5,-656.17 h60
  text "PCB VIEWED FROM BOTTOM SIDE" at 6246,-656.17 h60
  text ".TID" at 3224,-859.5 h60
  text "TID #:" at 3769.5,-859.5 h60
  text "TEXAS INSTRUMENTS" at 904.5,-1064.84 h60
  text ".Print_Time" at 2169,-1064.84 h60
  text ".Print_Date" at 2898,-1064.84 h60
  text "GENERATED    :" at 3767.5,-1064.84 h60
  text ".plot_File_Name" at 5440.5,-1064.84 h60
  text "PLOT NAME =" at 6246,-1064.84 h60
M9 Title Sheet:
  drawing of 57 lines, arcs and shapes, not listed
  text "1" at 739.84,8036.5 h70
  text "2" at 3235.5,8036.5 h70
  text "3" at 5724.84,8036.5 h70
  text "4" at 8231.51,8036.5 h70
  text "5" at 10730.5,8036.5 h70
  text "6" at 13235.5,8036.5 h70
  text "A" at -416.5,6893.5 h70
  text "A" at 14383.5,6893.5 h70
  text "B" at -416.5,4513.5 h70
  text "B" at 14383.5,4513.5 h70
  text "C" at -416.5,2138.5 h70
  text "C" at 14383.5,2138.5 h70
  text "PROJECT TITLE:" at 11343.5,277.5 h45
  text ".PRJ_Title" at 11393.5,144.17 h70
  text "DESIGNED FOR:" at 11343.5,-23.5 h45
  text ".PRJ_Customer" at 11393.5,-163.5 h70
  text "D" at -416.5,-231.5 h70
  text "D" at 14383.5,-231.5 h70
  text "FILE NAME:" at 11343.5,-323.5 h45
  text ".PCB_File_Name_No_Path" at 11393.5,-443.5 h70
  text "Texas Instruments (TI) and/or its licensors do not warrant the accuracy or completeness of this specification" at 6374,-605.34 h45
  text "ENGINEER:" at 11343.5,-613.5 h45
  text "LAYOUT BY:" at 12848.5,-613.5 h45
  text "or any information contained therein. TI and/or its licensors do not warrant that this design will meet" at 6329.01,-718 h45
  text ".PRJ_Engineer" at 11393.5,-768.49 h70
  text ".PCB_Layout" at 12899,-768.49 h70
  text "the specifications, will be suitable for your application or fit for any particular purpose, or will operate in" at 6329.01,-830.67 h45
  text ".Layer_Name" at 577,-858.49 h60
  text "ALTIUM DESIGNER VERSION:" at 12848.5,-923.5 h45
  text "an implementation. TI and/or its licensors do not warrant that the design is production worthy. You should" at 6329.01,-943.33 h45
  text "completely validate and test your design implementation to confirm the system functionality for your application." at 6374,-1056 h45
  text ".print_Scale" at 11393.5,-1056.83 h70
  text ".Application_BuildNumber" at 12899,-1056.83 h70
  text "1" at 739.84,-1263.5 h70
  text "2" at 3235.5,-1263.5 h70
  text "3" at 5724.84,-1263.5 h70
  text "4" at 8231.51,-1263.5 h70
  text "5" at 10730.5,-1263.5 h70
  text "6" at 13235.5,-1263.5 h70
M10 Fab Notes:
  drawing of 189 lines, arcs and shapes, not listed
  text "DESIGN INFORMATION" at 12381.02,6028 h60
  text "MIN. TRACK WIDTH:" at 11736.46,5848 h60
  text "6" at 12832.7,5848 h60
  text "MIL" at 12987.46,5848 h60
  text "MIN. CLEARANCE:" at 11736.46,5716 h60
  text "0.2" at 12772.7,5716 h60
  text "mm" at 12987.46,5716 h60
  text "MIN. VIA PAD SIZE:" at 11736.46,5584 h60
  text "24" at 12802.71,5584 h60
  text "MIL" at 12987.46,5584 h60
  text "0.05mm (2MIL)" at 12431.46,5442.29 h60
  text "MINIMUM ANNULAR RING" at 11407.23,5438 h60
  text "EXTERNAL" at 13139.46,5438 h60
  text "PER" at 11607.23,5320 h60
  text "IPC-D-275 CLASS 2 LEVEL C" at 11827.23,5320 h60
  text "MIL, HOLES" at 13315.46,5207.71 h60
  text "+/-" at 12923,5207 h60
  text "+/-" at 13777,5207 h60
  text "REGISTRATION TOLERANCES:" at 11407.23,5202 h60
  text "METAL" at 12607,5202 h60
  text "5" at 13183.2,5202 h60
  text "3" at 14016.2,5202 h60
  text "MIL" at 14132.46,5202 h60
  text "+/-" at 13777,5089 h60
  text "HOLE SIZE TOLERANCE (UNLESS OTHERWISE SPECIFIED):" at 11407.23,5084 h60
  text "3" at 14016.2,5084 h60
  text "MIL" at 14132.46,5084 h60
  text "MATERIAL:" at 11332.46,4874.54 h60
  text "FR-4 High Tg" at 12318.9,4734.21 h60
  text "FR-408" at 11753.46,4725.64 h60
  text "OTHER" at 13241.46,4725.64 h60
  text "X" at 12164,4722 h60
  text "62 MIL (1.6mm) +/-10%" at 12073.56,4562.92 h60
  text "X" at 11930,4560 h60
  text "THICKNESS:" at 11407.23,4558.64 h60
  text "TOLERANCE:" at 11407.23,4400.64 h60
  text "X" at 12246.53,4400.64 h60
  text "ANSI IPC-6012 TYPE 3 CLASS 2" at 12433.48,4400.64 h60
  text "OTHER +/-" at 12433.46,4244.64 h60
  text "BOW & TWIST:" at 11407.23,4087.64 h60
  text "X" at 12246.53,4087.64 h60
  text "ANSI IPC-6012 TYPE 3 CLASS 2" at 12433.48,4087.64 h60
  text "OTHER +/-" at 12433.46,3929.13 h60
  text "DRILLING:" at 11332.46,3790.64 h60
  text "REFERENCE:" at 11407.23,3673.64 h60
  text "X" at 12055.46,3673.64 h60
  text "AS SHOWN" at 12242.46,3673.64 h60
  text "X" at 12956.46,3673.64 h60
  text "NC_DRILL FILES" at 13093.46,3673.64 h60
  text "PTH MIN COPPER THICKNESS:" at 11407.23,3515.64 h60
  text "X" at 12757.46,3515.64 h60
  text "1MIL" at 12894.46,3515.64 h60
  text "OTHER" at 13391.46,3515.64 h60
  text "BOARD FINISH:" at 11332.46,3356.64 h60
  text "SILKSCREEN:" at 11487.68,3238.64 h60
  text "X" at 12436.46,3238.64 h60
  text "TOP" at 12562.46,3238.64 h60
  text "X" at 12946.46,3238.64 h60
  text "BOTTOM" at 13073.46,3238.64 h60
  text "SILKSCREEN COLOR:" at 11487.68,3071.64 h60
  text "X" at 12435.42,3071.64 h60
  text "WHITE" at 12562.46,3071.64 h60
  text "OTHER" at 13073.46,3071.64 h60
  text "X" at 12566.42,2912.44 h60
  text "GREEN" at 12693.46,2912.44 h60
  text "OTHER" at 13311.46,2912.44 h60
  text "SOLDER RESIST COLOR:" at 11487.68,2901.64 h60
  text "X" at 12566.42,2742.44 h60
  text "MATTE" at 12693.46,2742.44 h60
  text "SEMI-GLOSS" at 13311,2741.8 h60
  text "IMMERSION GOLD (ENIG)" at 12393.46,2553.92 h60
  text "ENEPIG" at 13731,2550.64 h60
  text "SURFACE FINISH:" at 11332.46,2549.64 h60
  text "X" at 12206.51,2549.64 h60
  text "IMM. TIN/SILVER OR EQUIV" at 11662,2392.64 h60
  text "OTHER" at 13093.46,2392.64 h60
  text "ARRAY/PANEL:" at 11332.46,2213.64 h60
  text "CUT AND TRIM PER M1 BOARD OUTLINE" at 12393.46,2209.35 h60
  text "N.C. ROUTE" at 12393.46,2057.64 h60
  text "X" at 13072.46,2057.64 h60
  text "V. SCORE" at 13259.46,2057.64 h60
  text "CERTIFICATION:" at 11332.46,1920.64 h60
  text "MATERIALS AND WORKMANSHIP FOR ALL PCBS" at 12057.46,1920.64 h60
  text "TO MEET OR EXCEED THE REQUIREMENTS OF:" at 12057.46,1822.64 h60
  text "X" at 11683.96,1686.13 h60
  text "ANSI IPC-A-600F CLASS ->" at 11822.96,1686.13 h60
  text "X" at 13462.02,1686.13 h60
  text "2" at 13580.96,1686.14 h60
  text "1" at 13265.96,1684.64 h60
  text "3" at 13934.96,1684.64 h60
  text "X" at 11686.02,1526.64 h60
  text "UL 94V-0" at 11822.96,1526.64 h60
  text "X" at 12498.02,1526.64 h60
  text "RoHS" at 12634.96,1526.64 h60
  text "OTHER" at 13279.36,1526.64 h60
  text "PER ORDER" at 13676.42,1526.64 h60
  text "ADDITIONAL REQUIREMENTS:" at 11332.46,1385.64 h60
  text "MICROSECTION:" at 11407.23,1270.64 h60
  text "YES" at 12312.96,1270.64 h60
  text "REQUIRED" at 13174.46,1114.49 h60
  text "BARE BOARD ELEC. TEST:" at 11407.23,1111.64 h60
  text "NONE" at 12712.96,1111.64 h60
  text "X" at 13047.46,1111.64 h60
  text "PER ORDER" at 13766.46,1111.64 h60
  text "MANUFACTURER'S UL:" at 11407.23,954.64 h60
  text "RAIL" at 12572.96,950.35 h60
  text "METAL" at 13064.77,950.35 h60
  text "X" at 13440,950 h60
  text "SILK" at 13576.46,950.35 h60
  text ".Layer_Name" at 577,-858.49 h60
M11 Gerber Information:
  lines w10: -292,-930.17 6308,-930.17 ; -292,-726.83 6310,-726.83 ; -292,-523.5 -292,-1133.5 3713,-1133.5 6310,-1133.5 6310,-523.5 -291.5,-523.5 -291.5,-1133.5 1284,-1133.5 ; 2173,-1133.5 2173,-523.5 ; 3440,-726.83 3440,-523.5 ; 4280,-726.83 4280,-523.5 ; 4902,-1140 4902,-937.17
  text "ALL ARTWORK VIEWED FROM TOP SIDE" at -228.5,-655.67 h60
  text "BOARD #:" at 2248,-655.67 h60
  text ".PRJ_Number" at 2793.5,-655.67 h60
  text "REV:" at 3638,-655.67 h60
  text ".PCB_Rev" at 3929.5,-655.67 h60
  text "SVN REV:" at 4476,-655.67 h60
  text ".VersionControl_RevNumber" at 4982,-655.67 h60
  text "LAYER NAME =" at -228.5,-858.49 h60
  text "TID #:" at 2248,-859 h60
  text ".TID" at 2793.5,-859 h60
  text "PLOT NAME =" at -228.5,-1064.34 h60
  text ".plot_File_Name" at 577,-1064.34 h60
  text "GENERATED    :" at 2250,-1064.34 h60
  text ".Print_Date" at 3119.5,-1064.34 h60
  text ".Print_Time" at 3848.5,-1064.34 h60
  text "TEXAS INSTRUMENTS" at 5113,-1064.34 h60
M12 Stackup:
  drawing of 295 lines, arcs and shapes, not listed
  text "Layer" at 9785.74,7685 h60
  text "Name" at 10195.66,7685 h60
  text "Material" at 11135.4,7685 h60
  text "Thickness" at 11995.16,7685 h60
  text "Constant" at 12645,7685 h60
  text "Board Layer Stack" at 13214.86,7685 h60
  text "1" at 9785.74,7565 h60
  text "Top Overlay" at 10195.66,7565 h60
  text "2" at 9785.74,7445 h60
  text "Top Solder" at 10195.66,7445 h60
  text "Solder Resist" at 11135.4,7445 h60
  text "0.40mil" at 11995.16,7445 h60
  text "3.5" at 12645,7445 h60
  text "3" at 9785.74,7325 h60
  text "Top Layer" at 10195.66,7325 h60
  text "Copper" at 11135.4,7325 h60
  text "1.40mil" at 11995.16,7325 h60
  text "4" at 9785.74,7205 h60
  text "Dielectric 1" at 10195.66,7205 h60
  text "FR-4" at 11135.4,7205 h60
  text "8.00mil" at 11995.16,7205 h60
  text "4.2" at 12645,7205 h60
  text "5" at 9785.74,7085 h60
  text "Signal Layer 1" at 10195.66,7085 h60
  text "Copper" at 11135.4,7085 h60
  text "1.40mil" at 11995.16,7085 h60
  text "6" at 9785.74,6965 h60
  text "Dielectric 2" at 10195.66,6965 h60
  text "FR-4" at 11135.4,6965 h60
  text "40.00mil" at 11995.16,6965 h60
  text "4.2" at 12645,6965 h60
  text "7" at 9785.74,6845 h60
  text "Signal Layer 2" at 10195.66,6845 h60
  text "Copper" at 11135.4,6845 h60
  text "1.40mil" at 11995.16,6845 h60
  text "8" at 9785.74,6725 h60
  text "Dielectric 3" at 10195.66,6725 h60
  text "FR-4" at 11135.4,6725 h60
  text "8.00mil" at 11995.16,6725 h60
  text "4.2" at 12645,6725 h60
  text "9" at 9785.74,6605 h60
  text "Bottom Layer" at 10195.66,6605 h60
  text "Copper" at 11135.4,6605 h60
  text "1.40mil" at 11995.16,6605 h60
  text "10" at 9785.74,6485 h60
  text "Bottom Solder" at 10195.66,6485 h60
  text "Solder Resist" at 11135.4,6485 h60
  text "0.40mil" at 11995.16,6485 h60
  text "3.5" at 12645,6485 h60
  text "11" at 9785.74,6365 h60
  text "Bottom Overlay" at 10195.66,6365 h60
  text ".Layer_Name" at 577,-858.49 h60
M13 Component Bodies Top:
  text ".Layer_Name" at 577,-858.49 h60
M14 Component Bodies Bottom:
  text ".Layer_Name" at 577,-858.49 h60
M15 Courtyards Top:
  text ".Layer_Name" at 577,-858.49 h60
M16 Courtyards Bottom:
  text ".Layer_Name" at 577,-858.49 h60
Drill Drawing:
  circle w10: c5683.72,3017.64 r27.63
  lines w10: 5656.09,2741.38 5656.09,2755.19 5669.9,2769 5656.09,2782.82 5656.09,2796.63 5669.9,2796.63 5683.72,2782.82 5697.53,2796.63 5711.34,2796.63 5711.34,2782.82 5697.53,2769 5711.34,2755.19 5711.34,2741.38 5697.53,2741.38 5683.72,2755.19 5669.9,2741.38 5656.09,2741.38 ; 5656.09,2920.95 5711.34,2920.95 5683.72,2865.7 5656.09,2920.95 ; 5656.09,3141.96 5683.72,3114.34 5711.34,3141.96 5683.72,3169.59 5656.09,3141.96 ; 5656.09,3252.47 5669.9,3252.47 5669.9,3238.66 5697.53,3238.66 5697.53,3252.47 5711.34,3252.47 5711.34,3280.1 5697.53,3280.1 5697.53,3293.91 5669.9,3293.91 5669.9,3280.1 5656.09,3280.1 5656.09,3252.47
  lines w12: 5606,2704.08 7584.02,2704.08 ; 5606,3325.68 7584.02,3325.68 ; 5943.86,2579.76 5943.86,3450 ; 6275.86,2579.76 6275.86,3450 ; 6912.43,2579.76 6912.43,3450 ; 7171.57,2579.76 7171.57,3450 ; 5606,2579.76 7584.02,2579.76 7584.02,3450 5606,3450 5606,2579.76
  text "Symbol" at 5680.59,3362.98 h72
  text "Quantity" at 5981.16,3362.98 h72
  text "Finished Hole Size" at 6313.16,3362.98 h72
  text "Plated" at 6949.72,3362.98 h72
  text "Hole Type" at 7208.86,3362.98 h72
  text "2" at 5981.16,3238.66 h60
  text "35.43mil (0.900mm)" at 6313.16,3238.66 h60
  text "NPTH" at 6949.72,3238.66 h60
  text "Round" at 7208.86,3238.66 h60
  text "4" at 5981.16,3114.34 h60
  text "88.98mil (2.260mm)" at 6313.16,3114.34 h60
  text "NPTH" at 6949.72,3114.34 h60
  text "Round" at 7208.86,3114.34 h60
  text "23" at 5981.16,2990.02 h60
  text "8.00mil (0.203mm)" at 6313.16,2990.02 h60
  text "PTH" at 6949.72,2990.02 h60
  text "Round" at 7208.86,2990.02 h60
  text "36" at 5981.16,2865.7 h60
  text "10.00mil (0.254mm)" at 6313.16,2865.7 h60
  text "PTH" at 6949.72,2865.7 h60
  text "Round" at 7208.86,2865.7 h60
  text "12" at 5981.16,2741.38 h60
  text "35.43mil (0.900mm)" at 6313.16,2741.38 h60
  text "PTH" at 6949.72,2741.38 h60
  text "Round" at 7208.86,2741.38 h60
  text "77 Total" at 5981.16,2617.06 h60
  text ".Layer_Name" at 577,-858.49 h60

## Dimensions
725,5149.41 to 1000.59,5149.41 on M2 Board Dimensions
1000.59,5149.41 to 1005.59,3279.33 on M2 Board Dimensions
1000.59,425 to 1000.59,2295.08 on M2 Board Dimensions
1000.59,425 to 725,425 on M2 Board Dimensions
0,-400 to 1000,-400 on M2 Board Dimensions
725,425 to 730,5149.41 on M2 Board Dimensions
520.67,4851.38 to 1204.92,4851.38 on M2 Board Dimensions
560.04,723.03 to 1165.55,723.03 on M2 Board Dimensions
